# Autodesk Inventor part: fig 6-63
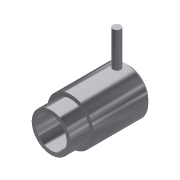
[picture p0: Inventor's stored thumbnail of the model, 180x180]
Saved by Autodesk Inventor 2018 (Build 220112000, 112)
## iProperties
Shininess: 77.0
Angle Display Precision: 2
Document Length Units: 11269
Document Angle Units: 11279
Document Time Units: 11290
Document Mass Units: 11283
Document Length Units Precision: 3
Document Angle Units Precision: 2
Compacted: True
Created: 2001-12
Part Number: fig 6-63
Document SubType Name: Modeling
Designer: Renu Muthoo
Density: 1 g/cm^3
Material: Generic
Appearance: Metal-AL-6061 (Polished)
Density: 0.0
Volumn: 0.0
Area: 0.0
PropertySet Name: Model Information
Control State: 0
Master: False
Checked Out: False
Author: Renu Muthoo
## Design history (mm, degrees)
sketch "Sketch2"
  geometry: L1 (-9.573, -4.327)-(-9.573, -5.327); L2 (-9.573, -5.327)-(-4.573, -5.327); L3 (-4.573, -5.327)-(-4.573, -6.327); L4 (-4.573, -6.327)-(9.427, -6.327); L5 (9.427, -6.327)-(10.427, -5.327); L6 (10.427, -5.327)-(10.427, -4.327); L7 (10.427, -4.327)-(-9.573, -4.327); L8 (-13.687, -0.327)-(14, -0.327)
  constraints: 16 end point, 5 parallel, 1 perpendicular, 1 vertical
  dimensions: "d9" = 20 distance of L6.end L1.start; "d10" = 5 distance of L1.end L2.end; "d11" = 12 diameter of L4 L8; "d12" = 10 diameter of L2 L8; "d13" = 8 diameter of L7 L8; "d14" = 45 deg angle of L5 L4; "d15" = 1 horizontal distance of L5.end L4.end
revolve "Revolution2" sketch "Sketch2" stored, may be unused: angle "d16" = 90 deg
workplane "Work Plane1"
workplane "Work Plane2"
sketch "Sketch3"
  geometry: L1 (-4, 8)-(4, 8) reference; C1 r 1 at (-0.098, 5)
  constraints: 1 centre point
  dimensions: "d18" = 3 distance from line of L1 C1.centre; "d19" = 2 diameter of C1
extrude "Extrusion1" join sketch "Sketch3" distance "d20" = 10; taper "d21" = 0 deg
body "Solid1"
other parameters: "d17" = -1
